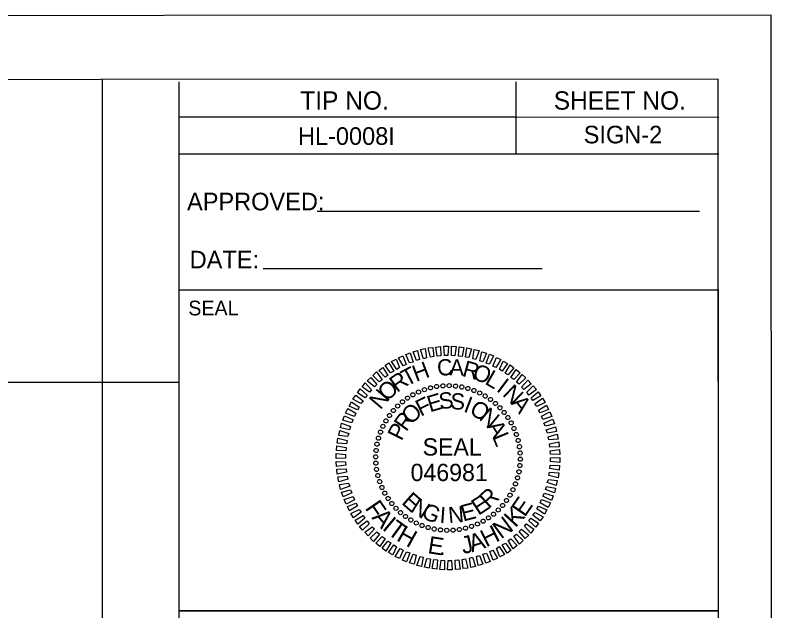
# Model space of a CAD drawing. Extents: x 1977705 to 1981198, y 827296 to 829291.
# Drawn here: x 1980758 to 1981020.7, y 828530 to 828736.6 of the extents above; entities that cross this region are included whole.
import ezdxf

# ---------------------------------------------------------------- set-up
doc = ezdxf.new("R2010")
doc.units = 0
for name, color, linetype in [('Level 13', 7, 'Continuous'), ('Level 3', 7, 'Continuous'), ('Level 32', 7, 'Continuous'), ('Level 34', 7, 'Continuous'), ('Level 7', 7, 'Continuous')]:
    doc.layers.add(name, color=color, linetype=linetype)

msp = doc.modelspace()

# ---------------------------------------------------------------- linework, layer by layer
at = {"layer": 'Level 13'}
for p, q in [((1980814.89, 828508.05), (1980814.89, 828529.99)), ((1980814.89, 828529.99), (1981001.67, 828529.99))]:
    msp.add_line(p, q, dxfattribs=at)
at = {"layer": 'Level 3'}
msp.add_lwpolyline([(1981020.16, 828736.58), (1979336.66, 828735.68), (1979337.25, 827640.68), (1981020.75, 827641.58)], close=True, dxfattribs=at)
at = {"layer": 'Level 32'}
for p, q in [((1980899.89, 828606.74), (1980899.89, 828606.74)), ((1980901.99, 828607.34), (1980901.99, 828607.34)), ((1980904.19, 828607.74), (1980904.19, 828607.74)), ((1980906.34, 828608.04), (1980906.34, 828608.04)), ((1980908.54, 828608.09), (1980908.54, 828608.09)), ((1980910.74, 828607.94), (1980910.74, 828607.94)), ((1980912.89, 828607.59), (1980912.89, 828607.59)), ((1980914.99, 828607.15), (1980914.99, 828607.15)), ((1980895.94, 828604.94), (1980895.94, 828604.94)), ((1980897.89, 828605.94), (1980897.89, 828605.94)), ((1980917.09, 828606.45), (1980917.09, 828606.45)), ((1980919.09, 828605.55), (1980919.09, 828605.55)), ((1980921.04, 828604.55), (1980921.04, 828604.55)), ((1980892.29, 828602.53), (1980892.29, 828602.53)), ((1980894.04, 828603.78), (1980894.04, 828603.78)), ((1980922.84, 828603.3), (1980922.84, 828603.3)), ((1980924.59, 828601.95), (1980924.59, 828601.95)), ((1980889.14, 828599.48), (1980889.14, 828599.48)), ((1980890.64, 828601.03), (1980890.64, 828601.03)), ((1980926.14, 828600.45), (1980926.14, 828600.45)), ((1980927.64, 828598.8), (1980927.64, 828598.8)), ((1980887.79, 828597.73), (1980887.79, 828597.73)), ((1980928.89, 828597.05), (1980928.89, 828597.05)), ((1980885.54, 828593.98), (1980885.54, 828593.98)), ((1980886.54, 828595.93), (1980886.54, 828595.93)), ((1980930.04, 828595.15), (1980930.04, 828595.15)), ((1980884.65, 828591.98), (1980884.65, 828591.98)), ((1980931.04, 828593.2), (1980931.04, 828593.2)), ((1980931.85, 828591.2), (1980931.85, 828591.2)), ((1980883.95, 828589.88), (1980883.95, 828589.88)), ((1980932.45, 828589.11), (1980932.45, 828589.11)), ((1980883.15, 828585.63), (1980883.15, 828585.63)), ((1980883.5, 828587.78), (1980883.5, 828587.78)), ((1980932.85, 828586.91), (1980932.85, 828586.91)), ((1980883, 828583.43), (1980883, 828583.43)), ((1980908.1, 828582.99), (1980908.1, 828582.99)), ((1980933.15, 828584.76), (1980933.15, 828584.76)), ((1980883.05, 828581.23), (1980883.05, 828581.23)), ((1980933.05, 828580.36), (1980933.05, 828580.36)), ((1980933.2, 828582.56), (1980933.2, 828582.56)), ((1980883.35, 828579.08), (1980883.35, 828579.08)), ((1980932.7, 828578.21), (1980932.7, 828578.21)), ((1980883.75, 828576.88), (1980883.75, 828576.88)), ((1980932.25, 828576.1), (1980932.25, 828576.1)), ((1980884.35, 828574.78), (1980884.35, 828574.78)), ((1980885.16, 828572.78), (1980885.16, 828572.78)), ((1980931.55, 828574), (1980931.55, 828574)), ((1980886.16, 828570.83), (1980886.16, 828570.83)), ((1980929.66, 828570.05), (1980929.66, 828570.05)), ((1980930.66, 828572), (1980930.66, 828572)), ((1980887.31, 828568.93), (1980887.31, 828568.93)), ((1980928.41, 828568.25), (1980928.41, 828568.25)), ((1980888.56, 828567.18), (1980888.56, 828567.18)), ((1980890.06, 828565.53), (1980890.06, 828565.53)), ((1980925.56, 828564.95), (1980925.56, 828564.95)), ((1980927.06, 828566.5), (1980927.06, 828566.5)), ((1980891.61, 828564.03), (1980891.61, 828564.03)), ((1980893.36, 828562.68), (1980893.36, 828562.68)), ((1980922.16, 828562.2), (1980922.16, 828562.2)), ((1980923.91, 828563.45), (1980923.91, 828563.45)), ((1980895.16, 828561.43), (1980895.16, 828561.43)), ((1980897.11, 828560.44), (1980897.11, 828560.44)), ((1980899.11, 828559.54), (1980899.11, 828559.54)), ((1980918.31, 828560.05), (1980918.31, 828560.05)), ((1980920.26, 828561.05), (1980920.26, 828561.05)), ((1980901.21, 828558.84), (1980901.21, 828558.84)), ((1980903.31, 828558.39), (1980903.31, 828558.39)), ((1980905.46, 828558.04), (1980905.46, 828558.04)), ((1980907.66, 828557.89), (1980907.66, 828557.89)), ((1980909.86, 828557.94), (1980909.86, 828557.94)), ((1980912.01, 828558.24), (1980912.01, 828558.24)), ((1980914.21, 828558.65), (1980914.21, 828558.65)), ((1980916.31, 828559.25), (1980916.31, 828559.25))]:
    msp.add_line(p, q, dxfattribs=at)
for points in [[(1980897.18, 828616.79), (1980896.03, 828619.79), (1980897.58, 828620.24), (1980898.23, 828617.14)], [(1980899.58, 828617.44), (1980898.53, 828620.59), (1980900.23, 828620.94), (1980900.63, 828617.69)], [(1980901.98, 828617.99), (1980901.18, 828621.19), (1980902.83, 828621.34), (1980903.18, 828618.14)], [(1980904.38, 828618.29), (1980903.83, 828621.49), (1980905.53, 828621.69), (1980905.58, 828618.44)], [(1980906.88, 828618.54), (1980906.63, 828621.79), (1980908.28, 828621.74), (1980908.08, 828618.49)], [(1980909.28, 828618.49), (1980909.28, 828621.74), (1980910.93, 828621.69), (1980910.48, 828618.44)], [(1980911.78, 828618.34), (1980911.98, 828621.59), (1980913.63, 828621.29), (1980912.98, 828618.14)], [(1980914.18, 828617.95), (1980914.63, 828621.15), (1980916.28, 828620.9), (1980915.38, 828617.8)], [(1980916.73, 828617.4), (1980917.23, 828620.65), (1980918.93, 828620.25), (1980917.78, 828617.15)], [(1980919.13, 828616.75), (1980919.88, 828619.85), (1980921.43, 828619.35), (1980920.18, 828616.4)], [(1980890.38, 828613.73), (1980888.53, 828616.43), (1980890.08, 828617.23), (1980891.33, 828614.33)], [(1980892.53, 828614.93), (1980890.93, 828617.73), (1980892.48, 828618.43), (1980893.63, 828615.38)], [(1980894.73, 828615.98), (1980893.43, 828618.88), (1980894.93, 828619.48), (1980895.98, 828616.29)], [(1980921.38, 828615.85), (1980922.53, 828619), (1980923.93, 828618.4), (1980922.53, 828615.5)], [(1980923.63, 828614.9), (1980924.88, 828617.85), (1980926.43, 828617.15), (1980924.73, 828614.35)], [(1980888.18, 828612.48), (1980886.33, 828615.03), (1980887.63, 828615.98), (1980889.28, 828613.08)], [(1980925.93, 828613.75), (1980927.28, 828616.6), (1980928.78, 828615.75), (1980926.88, 828613.15)], [(1980927.88, 828612.4), (1980929.63, 828615.3), (1980930.93, 828614.25), (1980928.98, 828611.8)], [(1980884.29, 828609.43), (1980882.08, 828611.63), (1980883.28, 828612.83), (1980885.24, 828610.13)], [(1980886.29, 828610.98), (1980884.13, 828613.38), (1980885.48, 828614.43), (1980887.23, 828611.63)], [(1980929.94, 828610.9), (1980931.78, 828613.65), (1980933.08, 828612.56), (1980930.89, 828610.2)], [(1980931.84, 828609.35), (1980933.88, 828611.96), (1980935.09, 828610.76), (1980932.79, 828608.61)], [(1980882.64, 828607.68), (1980880.09, 828609.73), (1980881.34, 828610.88), (1980883.44, 828608.48)], [(1980933.64, 828607.61), (1980935.79, 828609.96), (1980936.99, 828608.76), (1980934.39, 828606.81)], [(1980879.39, 828603.88), (1980876.69, 828605.58), (1980877.64, 828607.03), (1980880.04, 828604.83)], [(1980880.89, 828605.78), (1980878.29, 828607.73), (1980879.39, 828609.03), (1980881.59, 828606.68)], [(1980935.39, 828605.81), (1980937.69, 828608.06), (1980938.74, 828606.71), (1980936.09, 828604.81)], [(1980877.89, 828601.88), (1980875.09, 828603.37), (1980876.09, 828604.77), (1980878.69, 828602.78)], [(1980936.89, 828603.86), (1980939.34, 828605.96), (1980940.29, 828604.51), (1980937.49, 828602.91)], [(1980876.69, 828599.73), (1980873.84, 828600.97), (1980874.59, 828602.52), (1980877.29, 828600.68)], [(1980938.19, 828601.81), (1980940.84, 828603.71), (1980941.79, 828602.21), (1980938.89, 828600.81)], [(1980939.49, 828599.61), (1980942.29, 828601.36), (1980942.94, 828599.81), (1980940.09, 828598.66)], [(1980875.69, 828597.42), (1980872.59, 828598.57), (1980873.34, 828600.12), (1980876.19, 828598.52)], [(1980940.49, 828597.46), (1980943.44, 828598.96), (1980944.09, 828597.36), (1980940.99, 828596.36)], [(1980874.69, 828595.22), (1980871.59, 828596.12), (1980872.24, 828597.67), (1980875.24, 828596.27)], [(1980941.39, 828595.11), (1980944.44, 828596.41), (1980944.99, 828594.86), (1980941.89, 828594.06)], [(1980873.94, 828592.82), (1980870.84, 828593.47), (1980871.19, 828595.12), (1980874.34, 828593.87)], [(1980942.19, 828592.71), (1980945.39, 828593.86), (1980945.7, 828592.21), (1980942.55, 828591.66)], [(1980873.3, 828590.42), (1980870.2, 828590.82), (1980870.54, 828592.52), (1980873.7, 828591.47)], [(1980942.8, 828590.31), (1980945.95, 828591.26), (1980946.25, 828589.56), (1980943.1, 828589.26)], [(1980872.9, 828587.87), (1980869.7, 828588.17), (1980869.9, 828589.87), (1980873.15, 828589.07)], [(1980943.25, 828587.91), (1980946.5, 828588.61), (1980946.65, 828586.91), (1980943.45, 828586.71)], [(1980872.65, 828585.47), (1980869.4, 828585.57), (1980869.5, 828587.22), (1980872.75, 828586.67)], [(1980943.55, 828585.51), (1980946.8, 828585.91), (1980946.9, 828584.21), (1980943.65, 828584.31)], [(1980872.6, 828582.97), (1980869.35, 828582.82), (1980869.35, 828584.52), (1980872.6, 828584.17)], [(1980943.6, 828583.01), (1980946.85, 828583.16), (1980946.85, 828581.46), (1980943.6, 828581.81)], [(1980872.65, 828580.47), (1980869.4, 828580.07), (1980869.3, 828581.77), (1980872.55, 828581.67)], [(1980943.55, 828580.51), (1980946.8, 828580.41), (1980946.7, 828578.76), (1980943.45, 828579.31)], [(1980872.95, 828578.07), (1980869.7, 828577.37), (1980869.55, 828579.07), (1980872.75, 828579.27)], [(1980943.3, 828578.11), (1980946.5, 828577.81), (1980946.3, 828576.11), (1980943.05, 828576.91)], [(1980873.4, 828575.67), (1980870.25, 828574.72), (1980869.95, 828576.42), (1980873.1, 828576.72)], [(1980942.9, 828575.56), (1980946, 828575.16), (1980945.66, 828573.46), (1980942.5, 828574.51)], [(1980874.01, 828573.27), (1980870.81, 828572.12), (1980870.51, 828573.77), (1980873.65, 828574.32)], [(1980942.26, 828573.16), (1980945.36, 828572.51), (1980945.01, 828570.86), (1980941.86, 828572.11)], [(1980874.81, 828570.87), (1980871.76, 828569.57), (1980871.21, 828571.12), (1980874.31, 828571.92)], [(1980941.51, 828570.76), (1980944.61, 828569.86), (1980943.96, 828568.31), (1980940.96, 828569.71)], [(1980875.71, 828568.52), (1980872.76, 828567.02), (1980872.11, 828568.62), (1980875.21, 828569.62)], [(1980876.71, 828566.38), (1980873.91, 828564.62), (1980873.26, 828566.17), (1980876.11, 828567.32)], [(1980940.51, 828568.56), (1980943.61, 828567.41), (1980942.86, 828565.86), (1980940.01, 828567.46)], [(1980878.01, 828564.18), (1980875.36, 828562.27), (1980874.41, 828563.77), (1980877.31, 828565.18)], [(1980939.51, 828566.26), (1980942.36, 828565.01), (1980941.61, 828563.46), (1980938.91, 828565.31)], [(1980879.31, 828562.13), (1980876.86, 828560.03), (1980875.91, 828561.47), (1980878.71, 828563.08)], [(1980936.81, 828562.11), (1980939.51, 828560.41), (1980938.56, 828558.96), (1980936.16, 828561.16)], [(1980938.31, 828564.11), (1980941.11, 828562.61), (1980940.11, 828561.21), (1980937.51, 828563.21)], [(1980880.81, 828560.18), (1980878.51, 828557.93), (1980877.46, 828559.28), (1980880.11, 828561.18)], [(1980935.31, 828560.21), (1980937.91, 828558.26), (1980936.81, 828556.96), (1980934.61, 828559.31)], [(1980882.56, 828558.38), (1980880.41, 828556.03), (1980879.21, 828557.23), (1980881.81, 828559.18)], [(1980884.36, 828556.63), (1980882.32, 828554.03), (1980881.12, 828555.23), (1980883.41, 828557.38)], [(1980933.56, 828558.31), (1980936.11, 828556.26), (1980934.87, 828555.11), (1980932.76, 828557.51)], [(1980886.27, 828555.08), (1980884.42, 828552.33), (1980883.12, 828553.43), (1980885.31, 828555.78)], [(1980888.32, 828553.58), (1980886.57, 828550.68), (1980885.27, 828551.73), (1980887.22, 828554.18)], [(1980929.92, 828555), (1980932.07, 828552.6), (1980930.72, 828551.55), (1980928.97, 828554.35)], [(1980931.91, 828556.55), (1980934.12, 828554.36), (1980932.92, 828553.16), (1980930.96, 828555.85)], [(1980890.27, 828552.23), (1980888.92, 828549.38), (1980887.42, 828550.23), (1980889.32, 828552.83)], [(1980892.57, 828551.08), (1980891.32, 828548.13), (1980889.77, 828548.83), (1980891.47, 828551.63)], [(1980925.82, 828552.25), (1980927.67, 828549.55), (1980926.12, 828548.75), (1980924.87, 828551.65)], [(1980928.02, 828553.5), (1980929.87, 828550.95), (1980928.57, 828550), (1980926.92, 828552.9)], [(1980894.82, 828550.13), (1980893.67, 828546.98), (1980892.27, 828547.58), (1980893.67, 828550.48)], [(1980897.07, 828549.24), (1980896.32, 828546.14), (1980894.77, 828546.63), (1980896.02, 828549.59)], [(1980899.47, 828548.59), (1980898.97, 828545.34), (1980897.27, 828545.74), (1980898.42, 828548.84)], [(1980919.02, 828549.2), (1980920.17, 828546.2), (1980918.62, 828545.75), (1980917.97, 828548.85)], [(1980921.47, 828550), (1980922.77, 828547.1), (1980921.27, 828546.5), (1980920.22, 828549.7)], [(1980923.67, 828551.05), (1980925.27, 828548.25), (1980923.72, 828547.55), (1980922.57, 828550.6)], [(1980902.02, 828548.04), (1980901.57, 828544.84), (1980899.92, 828545.09), (1980900.82, 828548.19)], [(1980904.42, 828547.64), (1980904.22, 828544.39), (1980902.57, 828544.69), (1980903.22, 828547.84)], [(1980906.92, 828547.49), (1980906.92, 828544.24), (1980905.27, 828544.29), (1980905.72, 828547.54)], [(1980909.32, 828547.44), (1980909.57, 828544.19), (1980907.92, 828544.24), (1980908.12, 828547.49)], [(1980911.82, 828547.69), (1980912.37, 828544.49), (1980910.67, 828544.29), (1980910.62, 828547.54)], [(1980914.22, 828548), (1980915.02, 828544.8), (1980913.37, 828544.64), (1980913.02, 828547.84)], [(1980916.62, 828548.55), (1980917.67, 828545.4), (1980915.97, 828545.05), (1980915.57, 828548.3)]]:
    msp.add_lwpolyline(points, close=True, dxfattribs=at)
for centre, major_axis in [((1980897.89, 828605.9), (-0.293, 0.658)), ((1980899.92, 828606.7), (-0.235, 0.681)), ((1980902.02, 828607.32), (-0.175, 0.699)), ((1980904.16, 828607.76), (-0.113, 0.711)), ((1980906.34, 828608.01), (-0.051, 0.718)), ((1980908.52, 828608.07), (0.012, 0.72)), ((1980910.71, 828607.94), (0.075, 0.716)), ((1980912.87, 828607.61), (0.137, 0.707)), ((1980915, 828607.1), (0.198, 0.692)), ((1980917.08, 828606.41), (0.258, 0.672)), ((1980894.06, 828603.78), (-0.403, 0.597)), ((1980895.93, 828604.92), (-0.349, 0.63)), ((1980919.08, 828605.54), (0.315, 0.647)), ((1980921.01, 828604.5), (0.37, 0.617)), ((1980922.83, 828603.29), (0.423, 0.583)), ((1980890.67, 828601.02), (-0.5, 0.518)), ((1980892.31, 828602.47), (-0.453, 0.559)), ((1980924.54, 828601.93), (0.472, 0.544)), ((1980889.16, 828599.44), (-0.544, 0.472)), ((1980926.13, 828600.42), (0.518, 0.5)), ((1980927.58, 828598.79), (0.559, 0.453)), ((1980886.6, 828595.9), (-0.617, 0.37)), ((1980887.8, 828597.72), (-0.583, 0.423)), ((1980928.88, 828597.03), (0.597, 0.403)), ((1980885.55, 828593.97), (-0.647, 0.315)), ((1980930.03, 828595.16), (0.63, 0.349)), ((1980931.01, 828593.21), (0.658, 0.293)), ((1980884.68, 828591.97), (-0.672, 0.258)), ((1980931.81, 828591.17), (0.681, 0.235)), ((1980883.48, 828587.76), (-0.707, 0.137)), ((1980883.99, 828589.89), (-0.692, 0.198)), ((1980932.43, 828589.07), (0.699, 0.175)), ((1980883.16, 828585.6), (-0.716, 0.075)), ((1980932.87, 828586.93), (0.711, 0.113)), ((1980883.02, 828583.42), (-0.72, 0.012)), ((1980933.12, 828584.75), (0.718, 0.051)), ((1980933.18, 828582.57), (0.72, -0.012)), ((1980883.08, 828581.23), (-0.718, -0.051)), ((1980933.04, 828580.38), (0.716, -0.075)), ((1980883.33, 828579.06), (-0.711, -0.113)), ((1980932.72, 828578.22), (0.707, -0.137)), ((1980883.77, 828576.91), (-0.699, -0.175)), ((1980884.39, 828574.81), (-0.681, -0.235)), ((1980932.21, 828576.09), (0.692, -0.198)), ((1980885.19, 828572.78), (-0.658, -0.293)), ((1980930.65, 828572.01), (0.647, -0.315)), ((1980931.52, 828574.02), (0.672, -0.258)), ((1980886.17, 828570.82), (-0.63, -0.349)), ((1980929.6, 828570.09), (0.617, -0.37)), ((1980887.32, 828568.96), (-0.597, -0.403)), ((1980888.62, 828567.2), (-0.559, -0.453)), ((1980927.04, 828566.55), (0.544, -0.472)), ((1980928.4, 828568.26), (0.583, -0.423)), ((1980890.07, 828565.56), (-0.518, -0.5)), ((1980891.66, 828564.05), (-0.472, -0.544)), ((1980925.53, 828564.96), (0.5, -0.518)), ((1980893.37, 828562.69), (-0.423, -0.583)), ((1980895.19, 828561.49), (-0.37, -0.617)), ((1980922.14, 828562.21), (0.403, -0.597)), ((1980923.89, 828563.51), (0.453, -0.559)), ((1980897.12, 828560.44), (-0.315, -0.647)), ((1980899.12, 828559.57), (-0.258, -0.672)), ((1980901.2, 828558.88), (-0.198, -0.692)), ((1980914.18, 828558.66), (0.175, -0.699)), ((1980916.28, 828559.28), (0.235, -0.681)), ((1980918.31, 828560.09), (0.293, -0.658)), ((1980920.27, 828561.06), (0.349, -0.63)), ((1980903.33, 828558.37), (-0.137, -0.707)), ((1980905.49, 828558.05), (-0.075, -0.716)), ((1980907.68, 828557.92), (-0.012, -0.72)), ((1980909.86, 828557.97), (0.051, -0.718)), ((1980912.04, 828558.22), (0.113, -0.711))]:
    msp.add_ellipse(centre, major_axis=major_axis, ratio=0.999708, dxfattribs=at)
at = {"layer": 'Level 34'}
msp.add_line((1980814.89, 828609.21), (1979481.21, 828608.49), dxfattribs=at)
at = {"layer": 'Level 7'}
for p, q in [((1980814.89, 828688.54), (1980814.89, 828713.48)), ((1980931.75, 828688.53), (1980931.76, 828713.48)), ((1980931.75, 828688.53), (1980931.76, 828713.48)), ((1981001.98, 828713.48), (1981001.98, 828713.48)), ((1981001.98, 828713.48), (1981001.98, 828713.48)), ((1981001.98, 828713.48), (1981001.98, 828713.48)), ((1981001.98, 828713.48), (1981001.98, 828713.48)), ((1981001.98, 828713.48), (1981001.98, 828713.48)), ((1981001.98, 828713.48), (1981001.98, 828713.48)), ((1981001.98, 828713.48), (1981001.98, 828713.48)), ((1981001.98, 828713.48), (1981001.98, 828713.48)), ((1980814.89, 828701.27), (1980931.76, 828701.26)), ((1980931.76, 828701.26), (1981001.98, 828701.25)), ((1980814.89, 828688.54), (1981001.97, 828688.52)), ((1980814.89, 828641.37), (1980814.89, 828688.54)), ((1980862.71, 828668.62), (1980995.29, 828668.62)), ((1980844.03, 828648.72), (1980940.79, 828648.72))]:
    msp.add_line(p, q, dxfattribs=at)
for points in [[(1981001.8, 828714.37), (1979502.12, 828713.56), (1979502.69, 827663.79), (1981002.36, 827664.6)], [(1980814.89, 828641.37), (1981001.84, 828641.37), (1981001.84, 828529.99), (1980814.89, 828529.99)]]:
    msp.add_lwpolyline(points, close=True, dxfattribs=at)
msp.add_lwpolyline([(1980788.19, 828714.25), (1980788.19, 827737.43)], dxfattribs=at)

# ---------------------------------------------------------------- texts
at = {"layer": 'Level 32'}
for s, height, rotation, p in [('C', 5.65, 6.2507, (1980904.63, 828611.34)), ('A', 5.64, 359.0511, (1980908.58, 828611.64)), ('T', 5.76, 27.8506, (1980893.79, 828607.68)), ('H', 5.72, 20.6503, (1980897.04, 828609.34)), ('R', 5.69, 344.6519, (1980912.78, 828611.44)), ('O', 5.73, 337.452, (1980916.14, 828610.7)), ('R', 5.79, 35.0513, (1980890.39, 828605.48)), ('L', 5.77, 330.2517, (1980920.54, 828608.85)), ('O', 5.8, 42.2526, (1980886.94, 828602.38)), ('I', 5.79, 323.051, (1980924.59, 828606.45)), ('N', 5.79, 49.4543, (1980884.64, 828599.48)), ('N', 5.8, 315.8497, (1980926.74, 828604.9)), ('F', 5.75, 25.9978, (1980898.64, 828597.29)), ('E', 5.69, 16.6419, (1980901.84, 828598.79)), ('S', 5.65, 7.2864, (1980905.29, 828599.84)), ('S', 5.64, 357.9312, (1980908.89, 828599.89)), ('I', 5.72, 339.2204, (1980913.19, 828599.19)), ('O', 5.8, 44.7121, (1980895.34, 828594.34)), ('O', 5.77, 329.8643, (1980915.19, 828598.5)), ('A', 5.78, 308.648, (1980929.69, 828601.95)), ('R', 5.77, 54.0705, (1980893.6, 828591.88)), ('N', 5.8, 320.5074, (1980918.54, 828596.5)), ('P', 5.73, 63.4297, (1980892, 828588.68)), ('A', 5.76, 301.7911, (1980921.39, 828593.9)), ('L', 5.71, 292.4317, (1980923.35, 828590.45)), ('SEAL', 5.998, 0.0308, (1980899.3, 828583.84)), ('046981', 5.998, 0.0308, (1980895.13, 828574.98)), ('E', 5.8, 318.3077, (1980891.71, 828567.33)), ('E', 5.78, 33.1549, (1980918.66, 828562.9)), ('R', 5.8, 42.5122, (1980922.21, 828565.25)), ('F', 6.14, 304.4451, (1980879.14, 828565.63)), ('N', 5.78, 327.6648, (1980894.71, 828564.63)), ('E', 5.68, 14.4426, (1980913.36, 828560.94)), ('E', 6.14, 55.5238, (1980934.71, 828562.21)), ('G', 5.73, 337.0211, (1980898.51, 828562.39)), ('I', 5.64, 355.732, (1980905.06, 828560.49)), ('N', 5.64, 5.0872, (1980908.41, 828560.34)), ('K', 6.16, 47.2399, (1980931.44, 828558.6)), ('A', 6.16, 311.4617, (1980881.48, 828562.22)), ('I', 6.17, 320.302, (1980884.99, 828558.38)), ('N', 6.16, 36.5141, (1980926.49, 828554.68)), ('T', 6.16, 324.1039, (1980886.67, 828556.9)), ('H', 6.13, 330.9042, (1980889.91, 828554.55)), ('H', 6.12, 26.5301, (1980921.31, 828551.92)), ('A', 6.06, 17.6898, (1980916.37, 828550.26)), ('E', 6.02, 351.0885, (1980900.84, 828550.02)), ('J', 6.03, 12.432, (1980913.34, 828549.64)), ('.', 6, 358.1978, (1980904.98, 828549.37))]:
    msp.add_text(s, height=height, rotation=rotation, dxfattribs=at).set_placement(p)
at = {"layer": 'Level 7'}
for s, height, p in [('TIP NO.', 6.356, (1980856.88, 828703.81)), ('SHEET NO.', 6.356, (1980944.78, 828703.81)), ('HL-0008I', 6.108, (1980856.07, 828691.6)), ('SIGN-2', 6.108, (1980955.16, 828692.11)), ('APPROVED:', 6.108, (1980817.61, 828668.89)), ('DATE:', 6.108, (1980818.53, 828648.75)), ('SEAL', 5.093, (1980818.05, 828632.46))]:
    msp.add_text(s, height=height, rotation=359.9949, dxfattribs=at).set_placement(p)

doc.saveas('drawing.dxf')
